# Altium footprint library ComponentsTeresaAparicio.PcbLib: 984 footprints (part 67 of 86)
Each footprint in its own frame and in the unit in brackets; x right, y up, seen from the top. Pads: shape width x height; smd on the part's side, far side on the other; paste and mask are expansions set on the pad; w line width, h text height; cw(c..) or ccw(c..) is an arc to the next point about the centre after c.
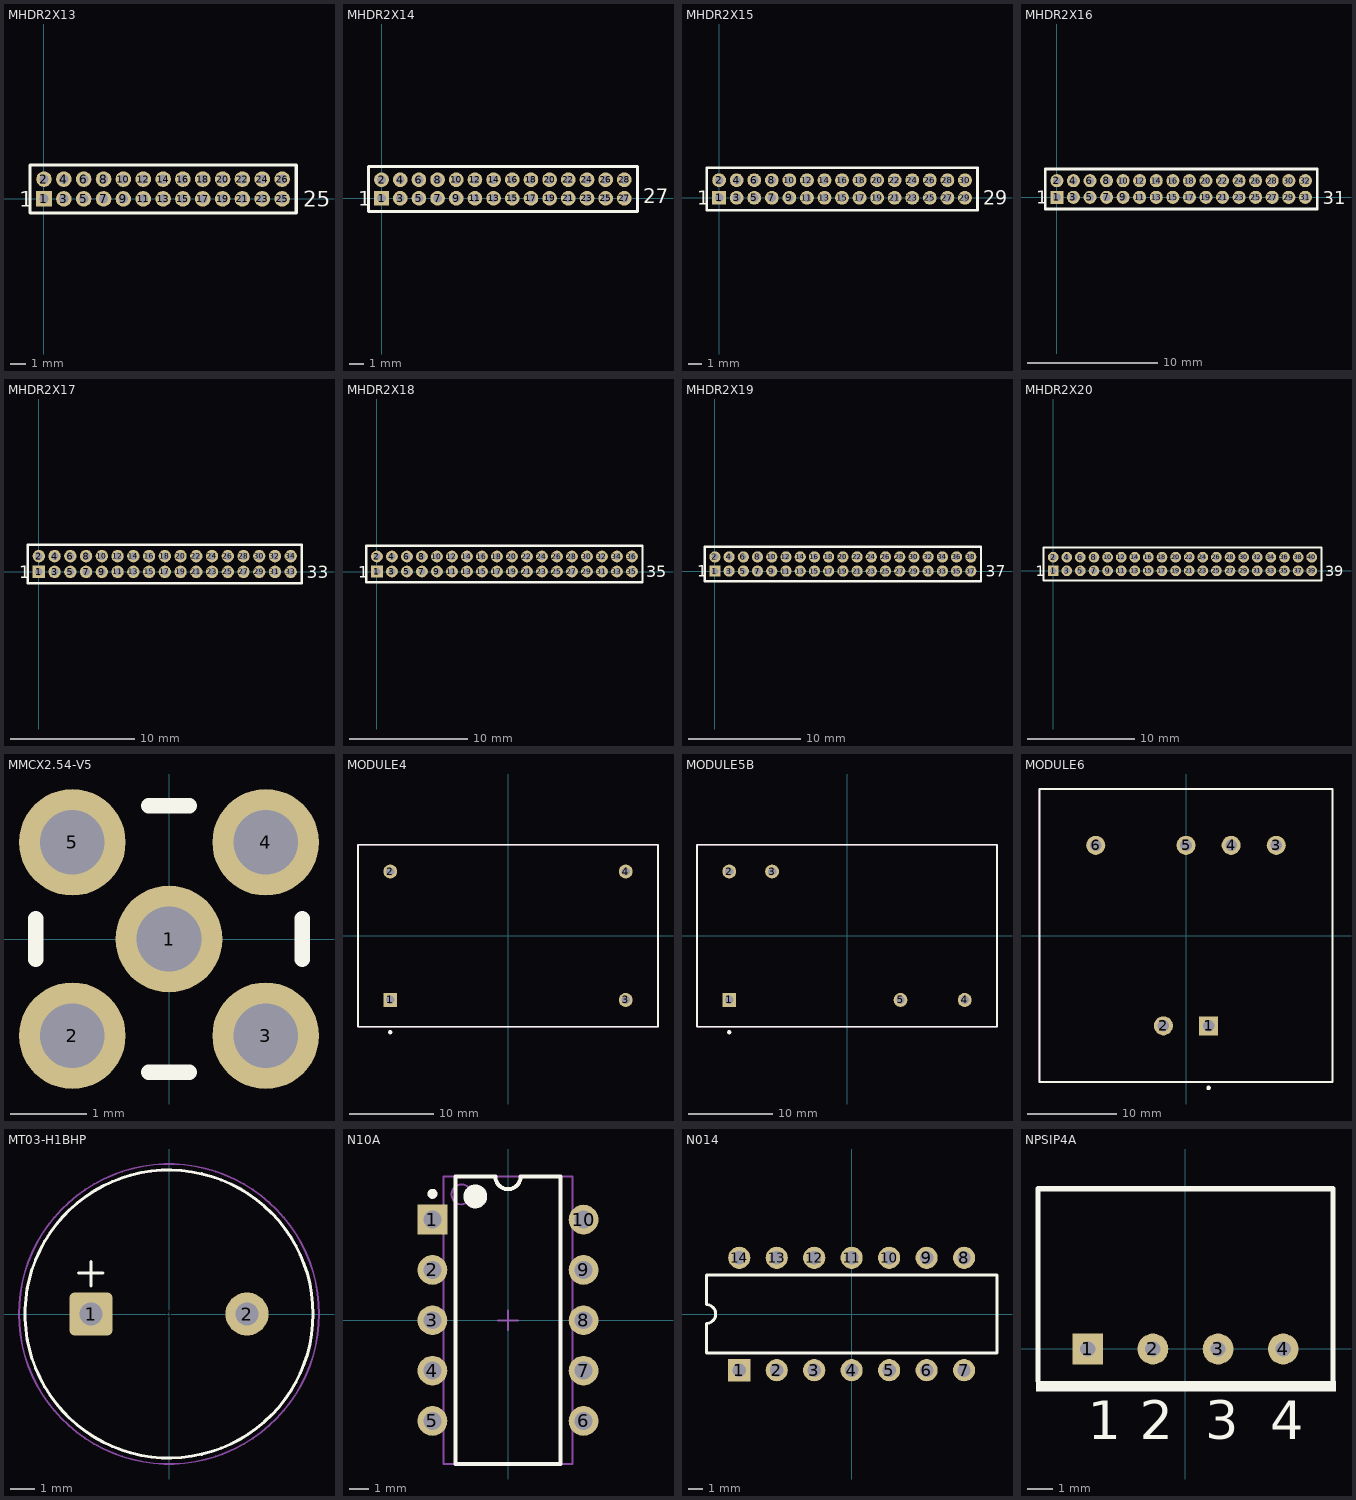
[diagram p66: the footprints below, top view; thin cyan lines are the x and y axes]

## MHDR2X13 [mm] "Connector; Header; 13x2 Position"
pads (26):
  rect 1x1 hole 0.6: 1(0,0)
  round 1 hole 0.6: 2(0,1.27) 3(1.27,0) 4(1.27,1.27) 5(2.54,0) 6(2.54,1.27) 7(3.81,0) 8(3.81,1.27) 9(5.08,0) 10(5.08,1.27) 11(6.35,0) 12(6.35,1.27) 13(7.62,0) 14(7.62,1.27) 15(8.89,0) 16(8.89,1.27) 17(10.16,0) 18(10.16,1.27) 19(11.43,0) 20(11.43,1.27) 21(12.7,0) 22(12.7,1.27) 23(13.97,0) 24(13.97,1.27) 25(15.24,0) 26(15.24,1.27)
Top Overlay:
  lines w0.2: -0.9,-0.9 16.14,-0.9 16.14,2.17 -0.9,2.17 -0.9,-0.9
  text "1" at -1.6,-0.508 h1
  text "25" at 16.6,-0.508 h1

## MHDR2X14 [mm] "Connector; Header; 14x2 Position"
pads (28):
  rect 1x1 hole 0.6: 1(0,0)
  round 1 hole 0.6: 2(0,1.27) 3(1.27,0) 4(1.27,1.27) 5(2.54,0) 6(2.54,1.27) 7(3.81,0) 8(3.81,1.27) 9(5.08,0) 10(5.08,1.27) 11(6.35,0) 12(6.35,1.27) 13(7.62,0) 14(7.62,1.27) 15(8.89,0) 16(8.89,1.27) 17(10.16,0) 18(10.16,1.27) 19(11.43,0) 20(11.43,1.27) 21(12.7,0) 22(12.7,1.27) 23(13.97,0) 24(13.97,1.27) 25(15.24,0) 26(15.24,1.27) 27(16.51,0) 28(16.51,1.27)
Top Overlay:
  lines w0.2: -0.9,-0.9 -0.9,2.17 17.41,2.17 17.41,-0.9 -0.9,-0.9
  text "27" at 17.8,-0.34 h1
  text "1" at -1.6,-0.508 h1

## MHDR2X15 [mm] "Connector; Header; 15x2 Position"
pads (30):
  rect 1x1 hole 0.6: 1(0,0)
  round 1 hole 0.6: 2(0,1.27) 3(1.27,0) 4(1.27,1.27) 5(2.54,0) 6(2.54,1.27) 7(3.81,0) 8(3.81,1.27) 9(5.08,0) 10(5.08,1.27) 11(6.35,0) 12(6.35,1.27) 13(7.62,0) 14(7.62,1.27) 15(8.89,0) 16(8.89,1.27) 17(10.16,0) 18(10.16,1.27) 19(11.43,0) 20(11.43,1.27) 21(12.7,0) 22(12.7,1.27) 23(13.97,0) 24(13.97,1.27) 25(15.24,0) 26(15.24,1.27) 27(16.51,0) 28(16.51,1.27) 29(17.78,0) 30(17.78,1.27)
Top Overlay:
  lines w0.2: -0.9,-0.9 18.68,-0.9 18.68,2.17 -0.9,2.17 -0.9,-0.9
  text "1" at -1.6,-0.508 h1
  text "29" at 19.1,-0.508 h1

## MHDR2X16 [mm] "Connector; Header; 16x2 Position"
pads (32):
  rect 1x1 hole 0.6: 1(0,0)
  round 1 hole 0.6: 2(0,1.27) 3(1.27,0) 4(1.27,1.27) 5(2.54,0) 6(2.54,1.27) 7(3.81,0) 8(3.81,1.27) 9(5.08,0) 10(5.08,1.27) 11(6.35,0) 12(6.35,1.27) 13(7.62,0) 14(7.62,1.27) 15(8.89,0) 16(8.89,1.27) 17(10.16,0) 18(10.16,1.27) 19(11.43,0) 20(11.43,1.27) 21(12.7,0) 22(12.7,1.27) 23(13.97,0) 24(13.97,1.27) 25(15.24,0) 26(15.24,1.27) 27(16.51,0) 28(16.51,1.27) 29(17.78,0) 30(17.78,1.27) 31(19.05,0) 32(19.05,1.27)
Top Overlay:
  lines w0.2: -0.9,-0.9 19.95,-0.9 19.95,2.17 -0.9,2.17 -0.9,-0.9
  text "1" at -1.6,-0.508 h1
  text "31" at 20.4,-0.522 h1

## MHDR2X17 [mm] "Connector; Header; 17x2 Position"
pads (34):
  rect 1x1 hole 0.6: 1(0,0)
  round 1 hole 0.6: 2(0,1.27) 3(1.27,0) 4(1.27,1.27) 5(2.54,0) 6(2.54,1.27) 7(3.81,0) 8(3.81,1.27) 9(5.08,0) 10(5.08,1.27) 11(6.35,0) 12(6.35,1.27) 13(7.62,0) 14(7.62,1.27) 15(8.89,0) 16(8.89,1.27) 17(10.16,0) 18(10.16,1.27) 19(11.43,0) 20(11.43,1.27) 21(12.7,0) 22(12.7,1.27) 23(13.97,0) 24(13.97,1.27) 25(15.24,0) 26(15.24,1.27) 27(16.51,0) 28(16.51,1.27) 29(17.78,0) 30(17.78,1.27) 31(19.05,0) 32(19.05,1.27) 33(20.32,0) 34(20.32,1.27)
Top Overlay:
  lines w0.2: -0.9,-0.9 21.22,-0.9 21.22,2.17 -0.9,2.17 -0.9,-0.9
  text "1" at -1.6,-0.508 h1
  text "33" at 21.6,-0.508 h1

## MHDR2X18 [mm] "Connector; Header; 18x2 Position"
pads (36):
  rect 1x1 hole 0.6: 1(0,0)
  round 1 hole 0.6: 2(0,1.27) 3(1.27,0) 4(1.27,1.27) 5(2.54,0) 6(2.54,1.27) 7(3.81,0) 8(3.81,1.27) 9(5.08,0) 10(5.08,1.27) 11(6.35,0) 12(6.35,1.27) 13(7.62,0) 14(7.62,1.27) 15(8.89,0) 16(8.89,1.27) 17(10.16,0) 18(10.16,1.27) 19(11.43,0) 20(11.43,1.27) 21(12.7,0) 22(12.7,1.27) 23(13.97,0) 24(13.97,1.27) 25(15.24,0) 26(15.24,1.27) 27(16.51,0) 28(16.51,1.27) 29(17.78,0) 30(17.78,1.27) 31(19.05,0) 32(19.05,1.27) 33(20.32,0) 34(20.32,1.27) 35(21.59,0) 36(21.59,1.27)
Top Overlay:
  lines w0.2: -0.9,-0.9 22.49,-0.9 22.49,2.17 -0.9,2.17 -0.9,-0.9
  text "1" at -1.6,-0.508 h1
  text "35" at 22.8,-0.501 h1

## MHDR2X19 [mm] "Connector; Header; 19x2 Position"
pads (38):
  rect 1x1 hole 0.6: 1(0,0)
  round 1 hole 0.6: 2(0,1.27) 3(1.27,0) 4(1.27,1.27) 5(2.54,0) 6(2.54,1.27) 7(3.81,0) 8(3.81,1.27) 9(5.08,0) 10(5.08,1.27) 11(6.35,0) 12(6.35,1.27) 13(7.62,0) 14(7.62,1.27) 15(8.89,0) 16(8.89,1.27) 17(10.16,0) 18(10.16,1.27) 19(11.43,0) 20(11.43,1.27) 21(12.7,0) 22(12.7,1.27) 23(13.97,0) 24(13.97,1.27) 25(15.24,0) 26(15.24,1.27) 27(16.51,0) 28(16.51,1.27) 29(17.78,0) 30(17.78,1.27) 31(19.05,0) 32(19.05,1.27) 33(20.32,0) 34(20.32,1.27) 35(21.59,0) 36(21.59,1.27) 37(22.86,0) 38(22.86,1.27)
Top Overlay:
  lines w0.2: -0.9,-0.9 23.76,-0.9 23.76,2.17 -0.9,2.17 -0.9,-0.9
  text "1" at -1.6,-0.508 h1
  text "37" at 24.2,-0.508 h1

## MHDR2X20 [mm] "Connector; Header; 20x2 Position"
pads (40):
  rect 1x1 hole 0.6: 1(0,0)
  round 1 hole 0.6: 2(0,1.27) 3(1.27,0) 4(1.27,1.27) 5(2.54,0) 6(2.54,1.27) 7(3.81,0) 8(3.81,1.27) 9(5.08,0) 10(5.08,1.27) 11(6.35,0) 12(6.35,1.27) 13(7.62,0) 14(7.62,1.27) 15(8.89,0) 16(8.89,1.27) 17(10.16,0) 18(10.16,1.27) 19(11.43,0) 20(11.43,1.27) 21(12.7,0) 22(12.7,1.27) 23(13.97,0) 24(13.97,1.27) 25(15.24,0) 26(15.24,1.27) 27(16.51,0) 28(16.51,1.27) 29(17.78,0) 30(17.78,1.27) 31(19.05,0) 32(19.05,1.27) 33(20.32,0) 34(20.32,1.27) 35(21.59,0) 36(21.59,1.27) 37(22.86,0) 38(22.86,1.27) 39(24.13,0) 40(24.13,1.27)
Top Overlay:
  lines w0.2: -0.9,-0.9 25.03,-0.9 25.03,2.17 -0.9,2.17 -0.9,-0.9
  text "1" at -1.6,-0.508 h1
  text "39" at 25.4,-0.508 h1

## MMCX2.54-V5 [mm] "Connector; RF Coaxial, MMCX, Thru-Hole; 5 Position; Vertical"
height 4.45
pads (5):
  round 1.4 hole 0.85: 1(0,0) 2(-1.27,-1.27) 3(1.27,-1.27) 4(1.27,1.27) 5(-1.27,1.27)
Top Overlay:
  lines w0.2: -1.75,-0.27 -1.75,0.27 ; -0.27,-1.75 0.27,-1.75 ; -0.27,1.75 0.27,1.75 ; 1.75,-0.27 1.75,0.27

## MODULE4 [mm] "DIP; 4 Round Pins; Row Space 27.94 mm; Pitch 15.24 mm"
height 14
pads (4):
  rect 1.65x1.65 hole 1: 1(-13.97,-7.62)
  round 1.65 hole 1: 2(-13.97,7.62) 3(13.97,-7.62) 4(13.97,7.62)
Top Overlay:
  circle w0.25: c-13.97,-11.45 r0.125
  lines w0.2: -17.8,-10.8 17.8,-10.8 17.8,10.8 -17.8,10.8 -17.8,-10.8
Mechanical 13:
  lines w0.1: -17.8,-10.8 17.8,-10.8 17.8,10.8 -17.8,10.8 -17.8,-10.8
3D body: height 14, standoff 0, extent -17.8,-10.8 17.8,10.8

## MODULE5B [mm] "DIP; 5 Round Pins; Row Space 15.24 mm; Pitch 2.54 mm"
height 14
pads (5):
  rect 1.65x1.65 hole 1: 1(-13.97,-7.62)
  round 1.65 hole 1: 2(-13.97,7.62) 3(-8.89,7.62) 4(13.97,-7.62) 5(6.35,-7.62)
Top Overlay:
  circle w0.25: c-13.97,-11.45 r0.125
  lines w0.2: -17.8,-10.8 17.8,-10.8 17.8,10.8 -17.8,10.8 -17.8,-10.8
Mechanical 13:
  lines w0.1: -17.8,-10.8 -17.8,10.8 17.8,10.8 17.8,-10.8 -17.8,-10.8
3D body: height 14, standoff 0, extent -17.8,-10.8 17.8,10.8

## MODULE6 [mm] "DIP; 6 Round Pins; Row Space 20.32 mm; Pitch 2.54 mm"
height 16.5
pads (6):
  rect 2.15x2.15 hole 1.3: 1(2.54,-10.16)
  round 2.15 hole 1.3: 2(-2.54,-10.16) 3(10.16,10.16) 4(5.08,10.16) 5(0,10.16) 6(-10.16,10.16)
Top Overlay:
  circle w0.25: c2.54,-17.15 r0.125
  lines w0.2: -16.5,-16.5 -16.5,16.5 16.5,16.5 16.5,-16.5 -16.5,-16.5
Mechanical 13:
  lines w0.1: -16.5,-16.5 -16.5,16.5 16.5,16.5 16.5,-16.5 -16.5,-16.5
3D body: height 16.5, standoff 0, extent -16.5,-16.5 16.5,16.5

## MT03-H1BHP [mm]
height 10.008
pads (3):
  round 0.508 on Mech14: 0(0,0)
  rrect25% 1.8x1.8 hole 0.965: 1(-3.25,0)
  round 1.8 hole 0.965: 2(3.25,0)
Top Overlay:
  circle w0.127: c0,0 r6
  lines w0.127: -3.766,1.7 -2.75,1.7 ; -3.252,1.165 -3.252,2.181
Mechanical 13:
  circle w0.076: c0.003,-0.012 r6
Mechanical 14:
  circle w0.076: c0,0 r6.25
3D body: height 10, standoff -2.8, extent -6.249,-6.249 6.25,6.25

## N10A [mm] "DIP; 10 Leads; Row Spacing 7.62 mm; Pitch 2.54 mm"
height 5.08
pads (10):
  rect 1.5x1.5 hole 0.9: 1(-3.81,5.08)
  round 1.5 hole 0.9: 2(-3.81,2.54) 3(-3.81,0) 4(-3.81,-2.54) 5(-3.81,-5.08) 6(3.81,-5.08) 7(3.81,-2.54) 8(3.81,0) 9(3.81,2.54) 10(3.81,5.08)
Top Overlay:
  circle w0.6: c-1.65,6.25 r0.3
  circle w0.25: c-3.81,6.38 r0.125
  lines w0.2: -2.65,-7.25 2.65,-7.25 2.65,7.25 0.635,7.25 cw(c0,7.25) -0.635,7.25 -2.65,7.25 -2.65,-7.25
Mechanical 13:
  circle w0.1: c-2.35,6.35 r0.5
  lines w0.1: -3.25,-7.25 3.25,-7.25 3.25,7.25 -3.25,7.25 -3.25,-7.25
Mechanical 15:
  lines w0.1: -0.5,0 0.5,0 ; 0,-0.5 0,0.5
3D body: height 5.08, standoff 0, extent -3.25,-7.25 3.25,7.25

## N014 [mm] "DIP; 14 Leads; Row Spacing 7.62 mm; Pitch 2.54 mm"
height 5.08
pads (14):
  rect 1.5x1.5 hole 0.9: 1(-7.62,-3.81)
  round 1.5 hole 0.9: 2(-5.08,-3.81) 3(-2.54,-3.81) 4(0,-3.81) 5(2.54,-3.81) 6(5.08,-3.81) 7(7.62,-3.81) 8(7.62,3.81) 9(5.08,3.81) 10(2.54,3.81) 11(0,3.81) 12(-2.54,3.81) 13(-5.08,3.81) 14(-7.62,3.81)
Top Overlay:
  lines w0.2: -9.85,-2.65 -9.85,-0.635 ccw(c-9.85,0) -9.85,0.635 -9.85,2.65 9.85,2.65 9.85,-2.65 -9.85,-2.65

## NPSIP4A [mm] "SIP; 4 Leads; Body 10 x 11.5 x 7.5 mm (typ); Pitch 2.54 mm"
height 10.6
pads (4):
  rect 1.2x1.2 hole 0.6: 1(-3.81,0)
  round 1.2 hole 0.6: 2(-1.27,0) 3(1.27,0) 4(3.81,0)
Top Overlay:
  rectangle: -5.83,-1.65 5.87,-1.25
  lines w0.2: -5.75,-1.25 -5.75,6.25 5.75,6.25 5.75,-1.25
  text "4" at 3.302,-3.52 h1.5
  text "3" at 0.762,-3.52 h1.5
  text "2" at -1.778,-3.52 h1.5
  text "1" at -3.81,-3.52 h1.5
